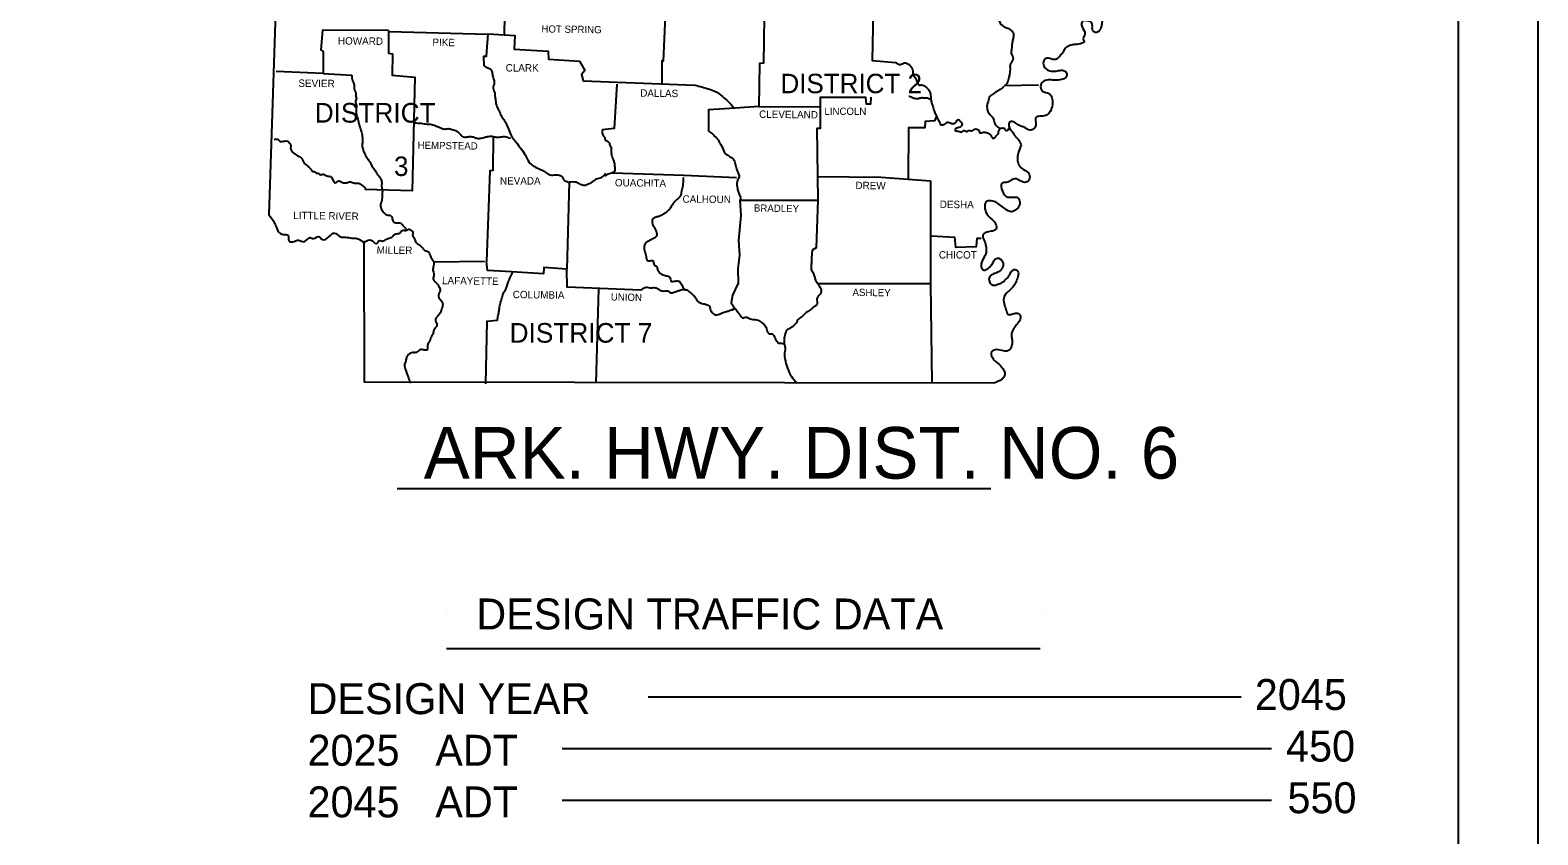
# Model space of a CAD drawing. Extents: x 76 to 6945, y -3933 to 2152.
# Drawn here: x 2483 to 3359, y 1052 to 1520 of the extents above; entities that cross this region are included whole.
import ezdxf

# ---------------------------------------------------------------- set-up
doc = ezdxf.new("R2010")
doc.units = 0
doc.layers.add('R_Draft', color=7, linetype='Continuous')
doc.layers.add('R_No Plot', color=7, linetype='Continuous')

msp = doc.modelspace()

# ---------------------------------------------------------------- linework, layer by layer
at = {"layer": 'R_Draft'}
for p, q in [((3313.39, 57.67), (3313.39, 2112.1)), ((2759.76, 1580.01), (2758.59, 1517.21)), ((3049.26, 1487.81), (3069.26, 1488.11)), ((2696.46, 1253.63), (3041.46, 1253.63)), ((2725.13, 1180.62), (2725.13, 1180.62)), ((3070.13, 1180.62), (3070.13, 1180.62)), ((2725.13, 1160.52), (3070.13, 1160.52)), ((2842.39, 1132.39), (3187, 1132.39)), ((2792.39, 1102.39), (3204.6, 1102.39)), ((2792.39, 1072.39), (3204.6, 1072.39))]:
    msp.add_line(p, q, dxfattribs=at)
for points in [[(2610.06, 1850.11), (2630.76, 1683.91), (2621.76, 1412.61)], [(2909.86, 1541.31), (2909.26, 1500.71), (2906.96, 1500.61), (2906.66, 1475.51)], [(2973.26, 1540.01), (2972.46, 1502.31), (2986.36, 1501.21)], [(2852.26, 1528.11), (2851.06, 1501.91), (2850.16, 1502.21), (2850.26, 1488.61)], [(2691.36, 1519.81), (2652.96, 1519.91), (2652.06, 1508.51), (2653.46, 1507.51), (2653.36, 1494.71), (2626.06, 1495.91)], [(2691.46, 1519.81), (2691.46, 1506.51), (2693.66, 1506.11), (2693.46, 1493.71), (2706.66, 1492.71), (2705.06, 1426.61), (2677.86, 1427.31)], [(2691.66, 1519.11), (2748.86, 1517.61)], [(2746.96, 1499.31), (2746.76, 1504.81), (2748.36, 1504.91), (2749.36, 1517.81), (2764.76, 1516.81), (2764.36, 1508.91), (2784.26, 1507.81), (2784.36, 1503.01), (2802.36, 1501.91), (2805.46, 1496.51), (2803.56, 1494.11), (2804.46, 1490.41), (2869.66, 1488.01)], [(2653.36, 1494.71), (2669.96, 1493.71)], [(2824.06, 1488.51), (2822.56, 1462.81), (2815.66, 1462.01)], [(2892.82, 1474.66), (2877.46, 1473.71), (2877.36, 1461.21)], [(2906.66, 1475.51), (2892.82, 1474.66)], [(2906.66, 1475.51), (2942.06, 1475.31)], [(2942.29, 1475.31), (2942.36, 1462.81), (2940.26, 1462.71), (2940.86, 1421.21)], [(2971.72, 1480.98), (2971.56, 1476.91), (2969.26, 1476.91), (2968.86, 1480.81), (2942.26, 1480.81), (2942.29, 1475.31)], [(3009.86, 1470.01), (3008.66, 1467.31), (3003.36, 1466.81), (3003.06, 1463.21), (2993.56, 1463.21), (2993.46, 1433.31)], [(2752.26, 1458.21), (2752.06, 1438.31), (2750.26, 1438.11), (2748.26, 1385.41)], [(3046.86, 1462.91), (3047.75, 1462.98), (3048.42, 1463.28), (3049.18, 1463.05), (3049.39, 1462.39), (3050.12, 1461.69), (3050.96, 1461.59), (3051.56, 1462.08), (3052.21, 1462.91)], [(2796.36, 1431.51), (2795.06, 1381.11), (2781.56, 1382.01), (2781.46, 1378.31), (2762.79, 1379.4)], [(2821.56, 1437.11), (2862.96, 1435.61), (2893.66, 1434.41)], [(2940.56, 1434.81), (2977.66, 1434.51), (3006.46, 1432.31)], [(3006.46, 1432.31), (3006.46, 1372.51), (3007.26, 1315.01)], [(2895.66, 1421.11), (2896.22, 1412.21), (2894.75, 1397.73), (2895.38, 1389.12), (2894.34, 1381.36), (2894.55, 1372.96), (2891.4, 1365.83), (2890.56, 1361.42), (2892.87, 1358.07)], [(2895.66, 1421.11), (2940.86, 1421.21)], [(2940.86, 1421.21), (2939.86, 1393.41), (2937.66, 1392.01)], [(2677.06, 1396.51), (2677.26, 1315.61), (3043.76, 1315.01)], [(3006.96, 1400.41), (3020.36, 1399.61), (3020.96, 1393.81), (3033.06, 1394.21), (3033.56, 1399.11), (3035.86, 1399.11)], [(2747.14, 1385.4), (2717.96, 1385.11)], [(2762.79, 1379.4), (2748.96, 1380.21), (2748.26, 1385.41)], [(2837.96, 1368.91), (2795.26, 1370.51), (2795.06, 1380.61)], [(2813.46, 1369.61), (2811.86, 1314.71)], [(2941.46, 1372.61), (3006.46, 1372.61)], [(2754.66, 1351.11), (2748.46, 1350.71), (2747.76, 1314.41)]]:
    msp.add_lwpolyline(points, dxfattribs=at)
for points in [[(3127.96, 1585.11), (3125.66, 1582.21), (3122.26, 1584.01), (3122.26, 1586.41), (3122.76, 1588.91), (3121.56, 1590.51), (3119.46, 1589.81), (3119.46, 1586.71), (3119.26, 1583.71), (3118.66, 1579.41), (3120.06, 1578.11), (3123.26, 1577.71), (3125.56, 1577.11), (3126.96, 1574.81), (3126.86, 1572.01), (3125.76, 1569.31), (3124.16, 1567.11), (3121.66, 1566.31), (3119.66, 1567.61), (3118.86, 1570.21), (3117.96, 1572.51), (3116.26, 1574.21), (3114.46, 1572.31), (3114.06, 1568.81), (3114.16, 1565.81), (3114.16, 1561.71), (3116.76, 1559.01), (3118.36, 1555.91), (3117.86, 1553.11), (3115.96, 1549.81), (3115.16, 1546.91), (3114.36, 1543.01), (3114.46, 1538.71), (3113.76, 1534.51), (3112.36, 1531.71), (3109.76, 1529.41), (3108.06, 1527.91), (3106.66, 1526.41), (3105.96, 1523.41), (3105.46, 1521.31), (3103.56, 1518.81), (3102.06, 1518.61), (3100.86, 1519.61), (3100.46, 1521.31), (3100.46, 1523.01), (3099.66, 1524.71), (3097.16, 1525.41), (3095.16, 1525.31), (3094.26, 1523.91), (3095.56, 1520.01), (3096.06, 1517.51), (3095.36, 1514.11), (3095.76, 1513.71), (3092.16, 1511.81), (3089.26, 1511.51), (3086.86, 1510.81), (3084.56, 1509.31), (3083.46, 1507.11), (3081.86, 1505.31), (3080.46, 1503.61), (3078.56, 1502.81), (3076.46, 1503.21), (3073.66, 1503.51), (3072.06, 1501.51), (3072.56, 1498.61), (3074.46, 1496.91), (3077.26, 1496.11), (3080.16, 1496.31), (3082.96, 1496.61), (3085.56, 1495.21), (3085.06, 1492.51), (3082.56, 1491.21), (3078.86, 1490.81), (3075.86, 1491.11), (3072.26, 1490.31), (3070.46, 1488.01), (3071.46, 1484.51), (3075.36, 1483.11), (3077.16, 1479.81), (3077.26, 1476.71), (3075.96, 1472.61), (3074.16, 1470.71), (3070.66, 1469.91), (3067.96, 1469.41), (3067.56, 1464.81), (3066.36, 1462.51), (3064.26, 1461.81), (3061.26, 1463.31), (3059.46, 1464.01), (3057.26, 1465.01), (3054.46, 1466.71), (3052.36, 1466.41), (3052.96, 1462.01), (3053.16, 1461.81), (3055.56, 1458.51), (3057.96, 1455.91), (3059.06, 1452.81)], [(3024.36, 1552.91), (3024.66, 1548.81), (3027.06, 1548.21), (3028.06, 1547.11), (3028.56, 1544.81), (3030.26, 1543.81), (3032.56, 1542.41), (3033.96, 1541.41), (3034.96, 1539.81), (3035.56, 1537.21), (3037.16, 1535.51), (3039.36, 1534.71), (3040.96, 1532.81), (3041.96, 1530.11), (3043.56, 1528.91), (3045.16, 1526.81), (3045.96, 1525.91), (3047.36, 1523.51), (3048.76, 1522.31), (3049.76, 1521.61), (3051.36, 1521.11), (3053.36, 1519.81), (3054.66, 1517.81), (3054.66, 1516.31), (3054.16, 1514.01), (3053.76, 1511.61), (3053.56, 1508.91), (3053.36, 1506.51), (3054.26, 1504.51), (3053.76, 1501.51), (3052.76, 1499.91), (3052.66, 1497.71), (3052.36, 1494.41), (3051.96, 1492.51), (3051.06, 1489.41), (3049.76, 1487.81)], [(2746.96, 1499.31), (2748.56, 1498.31), (2750.46, 1497.41), (2751.46, 1495.91), (2751.86, 1493.61), (2752.56, 1491.11), (2752.76, 1488.51), (2752.16, 1487.11), (2752.96, 1483.91), (2753.26, 1481.71), (2753.56, 1479.11), (2754.36, 1475.61), (2755.66, 1473.21), (2756.86, 1470.31), (2758.86, 1467.21), (2760.56, 1463.81), (2761.36, 1462.01), (2762.86, 1458.31), (2764.76, 1455.81), (2767.76, 1452.01), (2770.46, 1448.11), (2771.96, 1445.21), (2774.26, 1442.01), (2776.86, 1440.41), (2780.16, 1438.71), (2782.26, 1437.71), (2784.66, 1436.01), (2787.76, 1435.81), (2790.06, 1435.81), (2792.16, 1434.91), (2793.16, 1433.11), (2794.96, 1431.91), (2796.36, 1431.51)], [(2986.36, 1501.21), (2987.86, 1500.21), (2989.96, 1500.31), (2991.36, 1500.91), (2992.46, 1500.81), (2993.96, 1499.91), (2994.96, 1498.71), (2995.66, 1497.81), (2996.16, 1496.41), (2996.16, 1495.11), (2996.66, 1493.31), (2997.26, 1492.61), (2998.06, 1491.31), (2998.56, 1490.11), (2998.86, 1489.31), (2999.96, 1488.01), (3000.96, 1488.11), (3001.86, 1488.01), (3003.06, 1487.31), (3004.86, 1485.91), (3005.16, 1485.51), (3006.36, 1482.91), (3006.56, 1481.31), (3006.76, 1479.21), (3007.16, 1477.21), (3007.96, 1475.01), (3008.36, 1473.51), (3009.26, 1471.41), (3009.86, 1470.01), (3010.66, 1468.21), (3011.86, 1466.21), (3012.36, 1465.01), (3014.06, 1465.11), (3015.26, 1465.61), (3016.16, 1466.41), (3017.26, 1466.31), (3018.46, 1465.91), (3020.06, 1465.61), (3021.06, 1466.21), (3021.56, 1466.61), (3021.66, 1467.51), (3022.56, 1468.01), (3023.56, 1467.31), (3024.66, 1465.71), (3024.66, 1464.71), (3024.26, 1464.11), (3022.96, 1463.31), (3021.16, 1462.71), (3020.66, 1462.01), (3022.36, 1461.21), (3025.06, 1461.01), (3025.76, 1461.61), (3027.56, 1461.11), (3028.26, 1461.61), (3030.66, 1461.51), (3031.76, 1462.31), (3033.96, 1462.21), (3034.66, 1461.71), (3034.66, 1460.81), (3036.46, 1460.41), (3037.76, 1460.71), (3039.46, 1460.21), (3040.96, 1459.41), (3041.76, 1458.31), (3042.76, 1457.11), (3043.66, 1457.41), (3044.36, 1458.31), (3045.86, 1459.91), (3045.86, 1460.91), (3046.26, 1461.61), (3046.76, 1462.61)], [(2669.96, 1493.71), (2670.46, 1490.71), (2671.36, 1488.11), (2671.46, 1486.11), (2672.36, 1483.11), (2672.36, 1482.01), (2672.66, 1479.81), (2672.26, 1478.61), (2672.76, 1476.21), (2672.66, 1474.41), (2672.66, 1472.91), (2672.76, 1470.41), (2673.56, 1468.21), (2674.36, 1464.91), (2674.86, 1463.21), (2675.66, 1460.61), (2676.16, 1457.41), (2676.26, 1455.01), (2676.06, 1452.81), (2676.66, 1450.31), (2677.76, 1447.81), (2679.16, 1445.41), (2680.86, 1442.71), (2682.06, 1440.61), (2683.56, 1438.31), (2684.76, 1436.41), (2686.56, 1434.01), (2687.36, 1432.01), (2687.36, 1429.21), (2687.76, 1426.61), (2687.66, 1423.71), (2687.46, 1421.11), (2686.76, 1417.51), (2687.26, 1415.81), (2689.16, 1413.31), (2690.36, 1412.61), (2692.46, 1412.21), (2693.46, 1410.81), (2694.06, 1408.71), (2696.16, 1408.01), (2698.46, 1407.81), (2699.56, 1406.61), (2701.06, 1405.01), (2701.56, 1404.21)], [(2869.66, 1488.01), (2877.46, 1485.81), (2881.46, 1484.31), (2885.46, 1481.41), (2888.76, 1478.51), (2892.06, 1474.81)], [(2993.76, 1481.52), (2993.96, 1481.51), (2995.26, 1481.21), (2996.36, 1480.61), (2997.16, 1480.41), (2998.36, 1480.21), (2999.36, 1480.31), (3001.06, 1480.71), (3002.06, 1480.71), (3003.66, 1480.71), (3004.66, 1480.61), (3006.16, 1479.81)], [(3049.06, 1487.21), (3046.96, 1485.51), (3045.16, 1484.51), (3043.26, 1483.11), (3040.96, 1481.41), (3039.86, 1478.51), (3039.26, 1474.51), (3040.06, 1472.11), (3041.86, 1470.01), (3043.06, 1468.31), (3043.96, 1465.31), (3046.16, 1463.21), (3046.86, 1462.91)], [(2706.46, 1466.11), (2710.26, 1465.81), (2713.76, 1465.41), (2716.46, 1465.11), (2719.26, 1464.11), (2721.76, 1463.21), (2723.36, 1462.51), (2726.06, 1462.71), (2728.36, 1462.21), (2730.96, 1461.31), (2732.86, 1459.61), (2734.06, 1458.31), (2736.36, 1457.81), (2738.26, 1458.11), (2740.56, 1457.91), (2743.16, 1457.11), (2745.26, 1457.21), (2746.96, 1457.61), (2748.96, 1458.11), (2751.46, 1458.31), (2753.36, 1457.91), (2755.86, 1457.81), (2758.76, 1458.11), (2762.36, 1457.11)], [(2624.86, 1456.41), (2627.06, 1456.51), (2628.56, 1455.21), (2629.46, 1455.31), (2631.06, 1455.51), (2632.56, 1455.41), (2633.66, 1454.51), (2634.56, 1452.91), (2634.46, 1451.41), (2634.56, 1450.81), (2635.26, 1449.51), (2636.46, 1448.51), (2637.76, 1447.51), (2638.96, 1446.71), (2640.96, 1445.41), (2641.16, 1445.01), (2641.96, 1443.41), (2642.96, 1442.11), (2644.16, 1441.31), (2645.46, 1439.91), (2646.06, 1439.31), (2647.06, 1437.91), (2648.16, 1437.81), (2649.66, 1436.91), (2650.76, 1436.61), (2651.96, 1435.81), (2653.16, 1436.21), (2654.66, 1435.61), (2656.66, 1435.01), (2657.76, 1434.81), (2659.06, 1432.91), (2660.36, 1431.31), (2661.96, 1432.21), (2664.96, 1431.31), (2666.86, 1431.21), (2668.56, 1431.71), (2669.86, 1431.61), (2672.26, 1431.01), (2673.76, 1431.01), (2675.36, 1430.41), (2676.86, 1429.21), (2677.86, 1427.91), (2677.86, 1427.31)], [(2815.66, 1462.01), (2815.66, 1460.11), (2816.36, 1458.31), (2817.06, 1457.51), (2817.36, 1456.21), (2818.26, 1455.61), (2819.56, 1454.41), (2820.26, 1452.71), (2820.76, 1451.61), (2820.76, 1450.21), (2820.86, 1448.81), (2821.06, 1447.11), (2822.26, 1444.11), (2822.56, 1442.91), (2822.76, 1441.91), (2822.86, 1440.21), (2822.86, 1438.21), (2821.56, 1437.11)], [(2877.36, 1461.21), (2879.66, 1459.71), (2881.56, 1457.71), (2882.96, 1456.21), (2883.86, 1454.51), (2885.06, 1452.51), (2886.76, 1448.71), (2888.26, 1447.41), (2890.36, 1446.11), (2891.66, 1445.21), (2892.96, 1442.31), (2893.56, 1439.41), (2894.66, 1436.81), (2895.16, 1434.81), (2894.26, 1432.81), (2894.06, 1428.81), (2894.66, 1426.11), (2895.46, 1424.11), (2895.96, 1421.81), (2895.66, 1421.11)], [(3059.06, 1452.81), (3058.06, 1450.51), (3056.96, 1446.51), (3057.26, 1443.11), (3058.76, 1440.21), (3061.16, 1438.61), (3063.76, 1436.31), (3063.56, 1432.81), (3062.06, 1431.51), (3058.56, 1432.41), (3055.86, 1433.61), (3053.56, 1432.91), (3050.46, 1431.41), (3048.16, 1431.11), (3048.26, 1426.31), (3051.36, 1422.91), (3054.06, 1422.91), (3057.16, 1422.51), (3058.26, 1418.91), (3056.46, 1415.91), (3053.46, 1414.41), (3049.66, 1416.21), (3046.96, 1418.11), (3044.26, 1419.91), (3040.86, 1420.81), (3038.96, 1420.41), (3038.06, 1416.21), (3039.66, 1412.41), (3042.26, 1409.81), (3044.66, 1406.41), (3044.26, 1403.91), (3042.46, 1403.21), (3039.26, 1402.51), (3037.36, 1401.51), (3036.86, 1400.71), (3037.86, 1397.31), (3038.76, 1393.61), (3038.76, 1390.81), (3037.66, 1388.21), (3035.96, 1384.21), (3036.16, 1381.61), (3037.36, 1380.41), (3038.86, 1380.81), (3040.86, 1382.21), (3042.16, 1383.81), (3043.26, 1385.81), (3045.36, 1387.51), (3047.96, 1386.01), (3048.56, 1382.91), (3047.06, 1380.21), (3044.96, 1379.01), (3042.36, 1378.01), (3040.46, 1375.81), (3040.96, 1373.21), (3042.46, 1371.81), (3046.16, 1372.51), (3048.66, 1373.61), (3050.06, 1375.01), (3051.76, 1376.71), (3052.66, 1378.41), (3053.96, 1380.21), (3056.26, 1380.71), (3057.36, 1379.21), (3056.96, 1375.81), (3055.56, 1372.61), (3053.66, 1369.91), (3051.56, 1368.01), (3048.96, 1363.91), (3049.46, 1360.11), (3050.46, 1357.01), (3051.86, 1354.61), (3054.26, 1355.11), (3056.96, 1355.41), (3058.56, 1354.11), (3058.36, 1351.31), (3056.36, 1348.61), (3054.46, 1346.01), (3053.46, 1342.41), (3053.86, 1339.91), (3053.86, 1337.61), (3053.06, 1335.11), (3051.66, 1333.71), (3047.96, 1333.81), (3044.06, 1334.21), (3041.96, 1333.01), (3042.36, 1329.61), (3044.66, 1327.11), (3046.26, 1325.81), (3048.56, 1323.01), (3049.56, 1320.71), (3049.26, 1318.71), (3047.86, 1317.01), (3043.76, 1315.01)], [(2817.46, 1436.61), (2816.36, 1435.31), (2815.06, 1434.21), (2813.56, 1433.71), (2812.16, 1433.31), (2810.36, 1432.11), (2808.96, 1431.11), (2807.06, 1430.21), (2805.26, 1429.61), (2803.06, 1430.31), (2801.86, 1431.01), (2800.56, 1431.51), (2796.36, 1431.51)], [(2817.06, 1435.01), (2819.66, 1436.71), (2822.56, 1437.11)], [(2862.56, 1434.41), (2862.36, 1429.41), (2861.66, 1426.31), (2860.96, 1423.51), (2859.46, 1421.91), (2857.86, 1420.31), (2856.36, 1418.51), (2855.06, 1416.31), (2853.76, 1414.91), (2852.06, 1413.51), (2850.36, 1412.51), (2848.46, 1411.61), (2846.36, 1411.11), (2844.86, 1410.01), (2844.76, 1407.61), (2846.46, 1404.21), (2847.06, 1402.61), (2847.26, 1400.71), (2846.56, 1399.61), (2844.96, 1398.71), (2843.06, 1397.61), (2841.36, 1396.61), (2840.16, 1394.91), (2839.96, 1392.61), (2840.76, 1389.91), (2841.06, 1388.31), (2842.36, 1385.81), (2843.36, 1385.91), (2845.16, 1385.81), (2845.36, 1385.31), (2845.46, 1384.81), (2845.86, 1383.51), (2847.36, 1382.41), (2847.56, 1381.41), (2848.46, 1379.51), (2849.96, 1378.21), (2851.06, 1377.81), (2853.36, 1377.11), (2854.56, 1376.81), (2855.86, 1373.91), (2857.46, 1374.01), (2858.66, 1374.21), (2860.66, 1373.71), (2861.56, 1372.51), (2862.46, 1370.51), (2863.66, 1369.11), (2864.46, 1369.11)], [(2621.76, 1412.61), (2624.66, 1408.81), (2625.86, 1406.11), (2627.56, 1402.61), (2630.06, 1401.21), (2632.96, 1400.71), (2633.56, 1397.31), (2636.56, 1397.21), (2638.96, 1397.91), (2642.26, 1397.01), (2645.76, 1399.41), (2647.76, 1398.81), (2650.66, 1400.01), (2652.86, 1398.21), (2656.66, 1399.81), (2660.06, 1402.01), (2663.26, 1399.91), (2666.36, 1399.61), (2670.06, 1399.11), (2672.96, 1398.91), (2675.56, 1397.61), (2677.46, 1396.31), (2677.06, 1396.51)], [(2677.06, 1396.51), (2680.56, 1398.01), (2682.06, 1397.51), (2683.36, 1396.21), (2684.86, 1396.21), (2685.66, 1397.41), (2687.16, 1397.51), (2688.36, 1397.41), (2689.66, 1398.21), (2690.76, 1398.71), (2692.26, 1399.21), (2693.36, 1399.61), (2694.36, 1400.71), (2696.16, 1401.61), (2698.26, 1402.31), (2698.86, 1403.31), (2699.86, 1403.71), (2701.86, 1403.61), (2703.16, 1404.21), (2704.26, 1403.71), (2705.26, 1403.01), (2705.46, 1400.41), (2706.26, 1399.01), (2707.46, 1396.51), (2709.16, 1395.21), (2710.76, 1393.91), (2711.36, 1393.11), (2713.06, 1391.61), (2714.56, 1391.11), (2715.26, 1390.01), (2716.36, 1387.41), (2717.96, 1385.11)], [(2717.96, 1385.11), (2717.36, 1382.21), (2717.26, 1379.91), (2717.76, 1377.21), (2717.26, 1375.91), (2718.06, 1374.01), (2719.56, 1372.51), (2720.66, 1370.91), (2721.36, 1368.61), (2720.46, 1366.01), (2721.46, 1363.31), (2722.36, 1362.31), (2722.86, 1360.71), (2722.16, 1357.61), (2721.26, 1355.31), (2719.26, 1353.01), (2718.66, 1351.91), (2718.96, 1350.41), (2719.46, 1348.01), (2718.96, 1347.31), (2717.66, 1345.61), (2717.26, 1343.71), (2716.36, 1342.11), (2715.36, 1339.21), (2714.06, 1336.81), (2713.86, 1334.11), (2711.86, 1334.11), (2709.56, 1334.11), (2707.46, 1332.61), (2705.56, 1332.51), (2703.26, 1331.61), (2701.86, 1329.71), (2701.36, 1327.61), (2700.76, 1325.61), (2701.36, 1322.21), (2702.26, 1319.81), (2702.96, 1317.91), (2704.16, 1314.81)], [(2937.66, 1392.01), (2937.36, 1388.91), (2937.26, 1386.01), (2937.06, 1383.21), (2937.06, 1381.11), (2938.26, 1378.81), (2938.96, 1376.61), (2939.66, 1374.71), (2941.06, 1372.21), (2942.36, 1370.31), (2942.76, 1367.61), (2941.96, 1366.21), (2940.46, 1364.11), (2940.36, 1360.31), (2938.56, 1359.11), (2936.26, 1357.11), (2934.96, 1356.21), (2933.56, 1355.31), (2932.06, 1353.71), (2929.86, 1352.21), (2928.26, 1349.71), (2926.46, 1347.81), (2924.96, 1346.81), (2922.86, 1345.51), (2921.96, 1343.51), (2921.26, 1339.81), (2921.56, 1337.11), (2921.96, 1334.71), (2921.46, 1331.71), (2921.96, 1328.41), (2922.46, 1325.81), (2923.26, 1323.51), (2924.36, 1320.91), (2925.76, 1318.51), (2928.76, 1314.81)], [(2754.66, 1351.11), (2755.16, 1354.31), (2755.66, 1356.81), (2755.96, 1359.21), (2756.56, 1361.91), (2757.46, 1364.81), (2758.26, 1367.21), (2759.36, 1368.91), (2760.06, 1370.91), (2760.96, 1373.31), (2761.86, 1375.81), (2763.46, 1379.01)], [(2837.96, 1368.91), (2839.56, 1370.01), (2841.06, 1370.61), (2842.56, 1370.31), (2844.16, 1370.11), (2845.56, 1370.31), (2847.36, 1370.01), (2848.86, 1369.11), (2850.56, 1368.41), (2852.26, 1368.41), (2853.76, 1368.41), (2855.06, 1367.51), (2857.46, 1367.61), (2859.46, 1368.41), (2861.46, 1369.01), (2864.16, 1369.31), (2866.56, 1367.61), (2868.26, 1366.21), (2869.66, 1364.61), (2870.66, 1362.81), (2871.76, 1361.81), (2873.56, 1361.11), (2874.96, 1360.81), (2876.66, 1360.31), (2877.56, 1359.91), (2878.36, 1358.01), (2879.66, 1355.41), (2882.16, 1354.51), (2885.26, 1355.71), (2887.76, 1356.41), (2889.56, 1357.01), (2890.66, 1357.41), (2891.66, 1357.51), (2891.36, 1357.71), (2892.56, 1358.01), (2893.66, 1357.21), (2894.36, 1356.11), (2895.56, 1354.51), (2896.66, 1353.11), (2897.76, 1352.61), (2898.86, 1353.21), (2900.36, 1352.71), (2901.66, 1352.21), (2903.16, 1351.81), (2904.46, 1351.71), (2906.16, 1351.31), (2907.46, 1350.61), (2908.66, 1349.91), (2909.86, 1348.61), (2911.06, 1346.61), (2911.46, 1345.01), (2912.86, 1343.41), (2914.16, 1343.41), (2916.06, 1340.81), (2916.76, 1339.81), (2918.26, 1338.01), (2919.36, 1338.01), (2921.46, 1337.61)]]:
    msp.add_spline(points, degree=3, dxfattribs=at)
at = {"layer": 'R_No Plot'}
msp.add_lwpolyline([(76.06, 2151.57), (3359.45, 2151.57), (3359.45, 18.24), (76.06, 18.24)], close=True, dxfattribs=at)

# ---------------------------------------------------------------- texts
at = {"layer": 'R_Draft'}
for s, height, rotation, p in [('HOT SPRING', 4.201, 359.22157, (2780.26, 1518.61)), ('HOWARD', 4.301, 359.51446, (2661.96, 1511.61)), ('PIKE', 4.299, 359.04516, (2716.86, 1510.81)), ('SEVIER', 4.301, 359.42706, (2638.96, 1487.01)), ('DALLAS', 4.3, 359.24615, (2837.66, 1481.31)), ('CLEVELAND', 4.301, 359.33765, (2906.76, 1469.01)), ('HEMPSTEAD', 4.199, 359.1885, (2708.26, 1451.01)), ('OUACHITA', 4.301, 359.20428, (2822.96, 1429.21)), ('DREW', 4.299, 359.22578, (2962.76, 1427.61)), ('CALHOUN', 4.301, 359.36341, (2862.26, 1419.71)), ('DESHA', 4.299, 359.3704, (3011.76, 1416.61)), ('LITTLE RIVER', 4.3007, 359.16968, (2635.96, 1410.21)), ('BRADLEY', 4.199, 359.1449, (2903.76, 1414.51)), ('MILLER', 4.3, 359.13195, (2684.46, 1390.11)), ('LAFAYETTE', 4.299, 359.18388, (2722.46, 1372.31)), ('COLUMBIA', 4.3, 359.21248, (2763.56, 1364.21)), ('ASHLEY', 4.201, 359.2361, (2961.06, 1365.51)), ('UNION', 4.201, 358.95837, (2820.56, 1362.81))]:
    msp.add_text(s, height=height, rotation=rotation, dxfattribs=at).set_placement(p)
for s, height, p in [('CLARK', 4.3, (2759.46, 1495.91)), ('DISTRICT 2', 11.3, (2919.2, 1483.3)), ('DISTRICT', 11.4, (2648.46, 1466.21)), ('LINCOLN', 4.2, (2944.76, 1470.71)), ('3', 11.3, (2694.56, 1435.21)), ('NEVADA', 4.3, (2756.16, 1430.21)), ('CHICOT', 4.3, (3011.26, 1387.21)), ('DISTRICT 7', 11.4, (2761.76, 1338.31)), ('ARK. HWY. DIST. NO. 6', 30, (2711.87, 1259.29)), ('DESIGN TRAFFIC DATA', 18, (2742.38, 1171.62)), ('DESIGN YEAR', 18, (2644.27, 1122.39)), ('2045', 18, (3194.91, 1124.81)), ('450', 18, (3213.05, 1094.81)), ('2025', 18, (2644.27, 1092.39)), (' ADT', 18, (2711.87, 1092.39)), ('2045', 18, (2644.27, 1062.39)), (' ADT', 18, (2711.87, 1062.39)), ('550', 18, (3213.9, 1064.81))]:
    msp.add_text(s, height=height, dxfattribs=at).set_placement(p)

doc.saveas('drawing.dxf')
